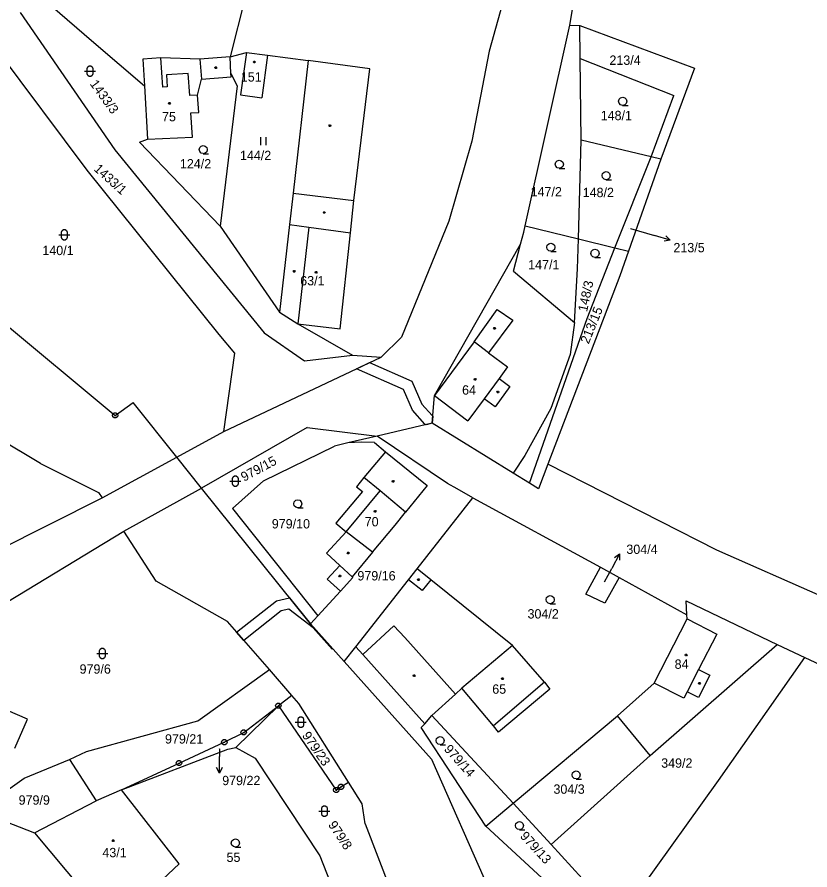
# Model space of a CAD drawing. Extents: x -850689 to -847910, y -1058374 to -1054747.
# Drawn here: x -849126.6 to -848982.2, y -1056250.1 to -1056094.9 of the extents above; entities that cross this region are included whole.
import ezdxf

# ---------------------------------------------------------------- set-up
doc = ezdxf.new("R2010")
doc.units = 0
for name, color, linetype in [('KN_BREMENA', 7, 'Continuous'), ('KN_HRANICE', 7, 'Continuous'), ('KN_KULTURY', 7, 'Continuous'), ('KN_MEZNIKY', 7, 'Continuous'), ('KN_PARCELY', 7, 'Continuous'), ('KN_SLUCKY', 7, 'Continuous'), ('KN_STAVEBNI', 7, 'Continuous')]:
    doc.layers.add(name, color=color, linetype=linetype)

# ---------------------------------------------------------------- blocks, each defined once
blk = doc.blocks.new('304')
blk.add_lwpolyline([(0, 0), (-0.38, 0.1), (-0.65, 0.37), (-0.75, 0.74), (-0.65, 1.11), (-0.38, 1.38), (-0.01, 1.48), (0.36, 1.38), (0.63, 1.11), (0.73, 0.73), (0.63, 0.35), (0.36, 0.08), (-0.02, -0.02), (0.98, -0.02)])
blk = doc.blocks.new('306')
for p, q in [((-0.5, 1.5), (-0.5, 0)), ((0.5, 0), (0.5, 1.5))]:
    blk.add_line(p, q)
blk = doc.blocks.new('316')
for points in [[(-0.5, 1.5), (-0.4, 1.79), (-0.15, 1.97), (0.16, 1.97), (0.41, 1.79), (0.51, 1.5), (0.51, 0.5), (0.41, 0.21), (0.16, 0.03), (-0.15, 0.03), (-0.4, 0.21), (-0.5, 0.5), (-0.5, 1.5)], [(-1, 1), (0.27, 1), (1, 1)]]:
    blk.add_lwpolyline(points)
blk = doc.blocks.new('NAHRADNI_SYMBOL')
blk.add_lwpolyline([(0.09, 0.15), (0.18, 0), (0.09, -0.15), (-0.09, -0.15), (-0.18, 0), (-0.09, 0.15), (0.09, 0.15)])
blk = doc.blocks.new('10292')
blk.add_line((0, 3), (0, 0))
blk.add_lwpolyline([(-0.5, 2), (0, 3), (0.5, 2)])
blk = doc.blocks.new('402')
blk.add_lwpolyline([(0.09, 0.15), (0.18, 0), (0.09, -0.15), (-0.09, -0.15), (-0.18, 0), (-0.09, 0.15), (0.09, 0.15)])
blk = doc.blocks.new('105')
blk.add_line((-0.12, 0), (0.12, 0))
blk.add_lwpolyline([(0.15, 0.48), (0.4, 0.3), (0.5, 0.01), (0.4, -0.28), (0.15, -0.46), (-0.16, -0.46), (-0.41, -0.28), (-0.51, 0.01), (-0.41, 0.3), (-0.16, 0.48), (0.15, 0.48)])

msp = doc.modelspace()

# ---------------------------------------------------------------- linework, layer by layer
at = {"layer": 'KN_BREMENA'}
for points in [[(-849062.4, -1056157.81), (-849054.72, -1056161.15), (-849052.89, -1056165.38), (-849051.02, -1056167.45), (-849050.9, -1056167.53), (-849051.02, -1056168.85), (-849052.13, -1056169.11), (-849052.32, -1056168.99), (-849054.59, -1056166.48), (-849056.24, -1056162.67), (-849064.8, -1056158.95)], [(-849086.62, -1056206.83), (-849079.37, -1056201.13), (-849076.98, -1056200.6), (-849073.16, -1056205.36), (-849069.12, -1056209.87), (-849069.22, -1056209.96), (-849072.69, -1056206.09), (-849077.08, -1056202.67), (-849078.49, -1056202.99), (-849085.3, -1056208.34)]]:
    msp.add_lwpolyline(points, close=True, dxfattribs=at)
at = {"layer": 'KN_HRANICE'}
for p, q in [((-849061.59, -1055999.43), (-849087.8, -1056102.18)), ((-849026.02, -1056048.69), (-849040.65, -1056101.15)), ((-849025.96, -1056096.38), (-849019.75, -1056059.38)), ((-849125.98, -1056094.1), (-849108.8, -1056119.1)), ((-849120.52, -1056092.73), (-849112.59, -1056099.57)), ((-849113.79, -1056122.8), (-849134.65, -1056094.95)), ((-849034.09, -1056132.93), (-849025.96, -1056096.38)), ((-849025.96, -1056096.38), (-849024.15, -1056096.47)), ((-849024.15, -1056096.47), (-849003.24, -1056104.25)), ((-849024.08, -1056102.46), (-849024.15, -1056096.47)), ((-849112.59, -1056099.57), (-849103.4, -1056107.43)), ((-849087.8, -1056102.18), (-849084.8, -1056101.39)), ((-849084.8, -1056101.39), (-849085.87, -1056109.07)), ((-849084.8, -1056101.39), (-849081, -1056101.88)), ((-849081, -1056101.88), (-849082.02, -1056109.6)), ((-849081, -1056101.88), (-849073.57, -1056102.83)), ((-849040.65, -1056101.15), (-849043.77, -1056117.52)), ((-849100.4, -1056102.37), (-849103.68, -1056102.59)), ((-849103.68, -1056102.59), (-849103.4, -1056107.43)), ((-849093.28, -1056102.6), (-849100.4, -1056102.37)), ((-849087.8, -1056102.18), (-849093.28, -1056102.6)), ((-849087.64, -1056105.2), (-849087.8, -1056102.18)), ((-849073.57, -1056102.83), (-849076.34, -1056126.97)), ((-849062.38, -1056104.35), (-849073.57, -1056102.83)), ((-849024.08, -1056102.46), (-849007, -1056109.17)), ((-849023.9, -1056117.35), (-849024.08, -1056102.46)), ((-849065.26, -1056128.29), (-849062.38, -1056104.35)), ((-849003.24, -1056104.25), (-849009.36, -1056120.8)), ((-849093.72, -1056109.11), (-849092.99, -1056106.2)), ((-849092.99, -1056106.2), (-849087.61, -1056105.82)), ((-849087.61, -1056105.82), (-849087.64, -1056105.2)), ((-849087.64, -1056105.2), (-849086.51, -1056107.42)), ((-849103.4, -1056107.43), (-849102.84, -1056117.15)), ((-849086.51, -1056107.42), (-849089.63, -1056132.97)), ((-849093.51, -1056112.28), (-849093.72, -1056109.11)), ((-849085.87, -1056109.07), (-849082.02, -1056109.6)), ((-849011.17, -1056120.37), (-849007, -1056109.17)), ((-849094.92, -1056112.37), (-849093.51, -1056112.28)), ((-849094.63, -1056116.77), (-849094.92, -1056112.37)), ((-849104.3, -1056117.68), (-849102.84, -1056117.15)), ((-849102.84, -1056117.15), (-849094.63, -1056116.77)), ((-849024.4, -1056135.3), (-849023.9, -1056117.35)), ((-849011.17, -1056120.37), (-849023.9, -1056117.35)), ((-849104.3, -1056117.68), (-849089.63, -1056132.97)), ((-849043.77, -1056117.52), (-849047.99, -1056132.07)), ((-849108.8, -1056119.1), (-849081.6, -1056152.37)), ((-849017.73, -1056136.93), (-849011.17, -1056120.37)), ((-849009.36, -1056120.8), (-849011.17, -1056120.37)), ((-849009.36, -1056120.8), (-849015.25, -1056137.54)), ((-849089.76, -1056152.69), (-849113.79, -1056122.8)), ((-849076.34, -1056126.97), (-849076.99, -1056132.65)), ((-849065.89, -1056134.2), (-849065.26, -1056128.29)), ((-849089.63, -1056132.97), (-849078.82, -1056148.64)), ((-849076.99, -1056132.65), (-849078.82, -1056148.64)), ((-849047.99, -1056132.07), (-849056.6, -1056153.2)), ((-849034.34, -1056134.08), (-849034.09, -1056132.93)), ((-849034.09, -1056132.93), (-849024.4, -1056135.3)), ((-849067.76, -1056151.67), (-849065.89, -1056134.2)), ((-849034.91, -1056136.25), (-849034.34, -1056134.08)), ((-849024.55, -1056140.74), (-849024.4, -1056135.3)), ((-849024.4, -1056135.3), (-849017.73, -1056136.93)), ((-849050.56, -1056163.8), (-849034.91, -1056136.25)), ((-849036.2, -1056141.14), (-849034.91, -1056136.25)), ((-849022.82, -1056149.76), (-849017.73, -1056136.93)), ((-849017.73, -1056136.93), (-849015.25, -1056137.54)), ((-849015.25, -1056137.54), (-849016.83, -1056142.02)), ((-849025.13, -1056150.52), (-849024.55, -1056140.74)), ((-849036.2, -1056141.14), (-849025.13, -1056150.52)), ((-849016.83, -1056142.02), (-849029.93, -1056176.3)), ((-849136.05, -1056144.68), (-849108.72, -1056167.41)), ((-849078.82, -1056148.64), (-849075.49, -1056150.72)), ((-849033.29, -1056179.77), (-849022.82, -1056149.76)), ((-849075.49, -1056150.72), (-849065.52, -1056156.43)), ((-849075.49, -1056150.72), (-849067.76, -1056151.67)), ((-849025.13, -1056150.52), (-849025.89, -1056156.3)), ((-849086.95, -1056156.09), (-849089.76, -1056152.69)), ((-849081.6, -1056152.37), (-849074.26, -1056157.48)), ((-849060.28, -1056156.81), (-849056.6, -1056153.2)), ((-849088.95, -1056170.34), (-849086.95, -1056156.09)), ((-849088.95, -1056170.34), (-849060.28, -1056156.81)), ((-849074.26, -1056157.48), (-849065.52, -1056156.43)), ((-849065.52, -1056156.43), (-849060.28, -1056156.81)), ((-849025.89, -1056156.3), (-849029.4, -1056166.16)), ((-849051.02, -1056168.85), (-849050.56, -1056163.8)), ((-849108.72, -1056167.41), (-849105.46, -1056165.09)), ((-849097.52, -1056174.99), (-849105.46, -1056165.09)), ((-849029.4, -1056166.16), (-849034.13, -1056174.69)), ((-849073.74, -1056169.61), (-849092.97, -1056180.66)), ((-849073.74, -1056169.61), (-849061.03, -1056171.18)), ((-849051.02, -1056168.85), (-849061.03, -1056171.18)), ((-849036.26, -1056177.94), (-849051.02, -1056168.85)), ((-849122.32, -1056176.18), (-849130.07, -1056171.57)), ((-849097.52, -1056174.99), (-849088.95, -1056170.34)), ((-849061.03, -1056171.18), (-849066.39, -1056172.42)), ((-849048.23, -1056179.78), (-849061.03, -1056171.18)), ((-849081.7, -1056179.33), (-849068.77, -1056173.01)), ((-849066.39, -1056172.42), (-849068.77, -1056173.01)), ((-849063.9, -1056172.26), (-849066.39, -1056172.42)), ((-849061.52, -1056172.32), (-849063.9, -1056172.26)), ((-849061.52, -1056172.32), (-849059.53, -1056174.06)), ((-849059.53, -1056174.06), (-849063.42, -1056178.73)), ((-849059.53, -1056174.06), (-849051.93, -1056180.18)), ((-849034.13, -1056174.69), (-849036.26, -1056177.94)), ((-849122.32, -1056176.18), (-849111.73, -1056181.42)), ((-849111.09, -1056182.39), (-849097.52, -1056174.99)), ((-849092.97, -1056180.66), (-849097.52, -1056174.99)), ((-849029.93, -1056176.3), (-849031.64, -1056180.79)), ((-848999.18, -1056191.91), (-849029.93, -1056176.3)), ((-849033.29, -1056179.77), (-849036.26, -1056177.94)), ((-849081.7, -1056179.33), (-849087.37, -1056184.36)), ((-849063.42, -1056178.73), (-849064.78, -1056180.4)), ((-849107.15, -1056188.47), (-849092.97, -1056180.66)), ((-849073.16, -1056205.36), (-849092.97, -1056180.66)), ((-849064.78, -1056180.4), (-849063.7, -1056181.26)), ((-849051.93, -1056180.18), (-849055.88, -1056185.01)), ((-849046.44, -1056180.79), (-849048.23, -1056179.78)), ((-849043.62, -1056182.43), (-849046.44, -1056180.79)), ((-849031.64, -1056180.79), (-849033.29, -1056179.77)), ((-849139, -1056196.47), (-849111.09, -1056182.39)), ((-849111.73, -1056181.42), (-849111.09, -1056182.39)), ((-849063.7, -1056181.26), (-849068.52, -1056187.03)), ((-849053.77, -1056195.35), (-849043.62, -1056182.43)), ((-849043.62, -1056182.43), (-849020.34, -1056195)), ((-849087.37, -1056184.36), (-849071.8, -1056203.9)), ((-849057.72, -1056187.39), (-849055.88, -1056185.01)), ((-849068.52, -1056187.03), (-849066.67, -1056188.57)), ((-849139.2, -1056207.88), (-849107.15, -1056188.47)), ((-849101.23, -1056197.58), (-849107.15, -1056188.47)), ((-849066.67, -1056188.57), (-849070.27, -1056192.49)), ((-849061.86, -1056192.28), (-849057.72, -1056187.39)), ((-848980.22, -1056200.29), (-848999.18, -1056191.91)), ((-849070.27, -1056192.49), (-849067.84, -1056194.72)), ((-849061.86, -1056192.28), (-849065.56, -1056196.81)), ((-849067.84, -1056194.72), (-849070.1, -1056197.19)), ((-849023.06, -1056199.93), (-849020.34, -1056195)), ((-849020.34, -1056195), (-849016.98, -1056196.89)), ((-849055.32, -1056197.33), (-849053.77, -1056195.35)), ((-849051.27, -1056197.35), (-849053.77, -1056195.35)), ((-849088.27, -1056204.94), (-849101.23, -1056197.58)), ((-849070.1, -1056197.19), (-849067.67, -1056199.42)), ((-849067.67, -1056199.42), (-849065.44, -1056196.92)), ((-849065.44, -1056196.92), (-849065.56, -1056196.81)), ((-849064.9, -1056209.52), (-849055.32, -1056197.33)), ((-849036.38, -1056209.25), (-849051.27, -1056197.35)), ((-849016.98, -1056196.89), (-849019.59, -1056201.6)), ((-849016.98, -1056196.89), (-849004.65, -1056203.72)), ((-849071.8, -1056203.9), (-849067.67, -1056199.42)), ((-849019.59, -1056201.6), (-849023.06, -1056199.93)), ((-849004.65, -1056203.72), (-849004.8, -1056201.15)), ((-849004.8, -1056201.15), (-848988.18, -1056209.07)), ((-849073.16, -1056205.36), (-849071.8, -1056203.9)), ((-849004.61, -1056204.42), (-849004.65, -1056203.72)), ((-849080.65, -1056213.66), (-849088.27, -1056204.94)), ((-849067.02, -1056212.21), (-849073.16, -1056205.36)), ((-849010.57, -1056216.16), (-849004.61, -1056204.42)), ((-849067.02, -1056212.21), (-849064.9, -1056209.52)), ((-849063.66, -1056210.9), (-849064.9, -1056209.52)), ((-849030.55, -1056215.98), (-849036.38, -1056209.25)), ((-849011.33, -1056229.27), (-848988.18, -1056209.07)), ((-848988.18, -1056209.07), (-848983.18, -1056211.44)), ((-849063.66, -1056210.9), (-849052.37, -1056223.51)), ((-848998.88, -1056233.84), (-848983.18, -1056211.44)), ((-848983.18, -1056211.44), (-848968.74, -1056218.34)), ((-849093.67, -1056222.96), (-849080.65, -1056213.66)), ((-849076.56, -1056218.35), (-849080.65, -1056213.66)), ((-849051.11, -1056229.98), (-849067.02, -1056212.21)), ((-849030.55, -1056215.98), (-849029.6, -1056217.21)), ((-849017.27, -1056222.1), (-849010.57, -1056216.16)), ((-849076.56, -1056218.35), (-849078.99, -1056220.24)), ((-849075.26, -1056219.83), (-849076.56, -1056218.35)), ((-849051.05, -1056222.04), (-849046.74, -1056218.12)), ((-849046.74, -1056218.12), (-849045.63, -1056217.05)), ((-849039.83, -1056223.87), (-849045.63, -1056217.05)), ((-849029.6, -1056217.21), (-849038.92, -1056225.07)), ((-849124.65, -1056222.67), (-849132.6, -1056219.32)), ((-849066.25, -1056234.12), (-849075.26, -1056219.83)), ((-849086.74, -1056227.86), (-849078.99, -1056220.24)), ((-849085.32, -1056225.1), (-849078.99, -1056220.24)), ((-849078.99, -1056220.24), (-849068.47, -1056235.58)), ((-849126.97, -1056227.99), (-849124.65, -1056222.67)), ((-849113.95, -1056228.54), (-849093.67, -1056222.96)), ((-849052.37, -1056223.51), (-849051.05, -1056222.04)), ((-849051.05, -1056222.04), (-849036.29, -1056237.99)), ((-849036.29, -1056237.99), (-849017.27, -1056222.1)), ((-849011.33, -1056229.27), (-849017.27, -1056222.1)), ((-849053.01, -1056224.22), (-849052.37, -1056223.51)), ((-849041.27, -1056242.15), (-849053.01, -1056224.22)), ((-849038.92, -1056225.07), (-849039.83, -1056223.87)), ((-849088.85, -1056226.88), (-849085.32, -1056225.1)), ((-849097.09, -1056230.68), (-849088.85, -1056226.88)), ((-849117.03, -1056230), (-849113.95, -1056228.54)), ((-849107.55, -1056235.54), (-849088.19, -1056228.17)), ((-849088.19, -1056228.17), (-849086.74, -1056227.86)), ((-849086.74, -1056227.86), (-849083.2, -1056229.78)), ((-849125.31, -1056233.41), (-849117.03, -1056230)), ((-849117.03, -1056230), (-849112.15, -1056237.55)), ((-849107.55, -1056235.54), (-849097.09, -1056230.68)), ((-849083.2, -1056229.78), (-849071.44, -1056247.58)), ((-849051.11, -1056229.98), (-849034.65, -1056267.35)), ((-849029.32, -1056245.51), (-849011.33, -1056229.27)), ((-849133.63, -1056239.4), (-849125.31, -1056233.41)), ((-849016.97, -1056259.04), (-848998.88, -1056233.84)), ((-849068.47, -1056235.58), (-849067.62, -1056235.02)), ((-849067.62, -1056235.02), (-849066.25, -1056234.12)), ((-849063.75, -1056238.1), (-849066.25, -1056234.12)), ((-849107.55, -1056235.54), (-849112.15, -1056237.55)), ((-849097.09, -1056249.01), (-849107.55, -1056235.54)), ((-849123.4, -1056243.38), (-849112.15, -1056237.55)), ((-849063.18, -1056241.7), (-849063.75, -1056238.1)), ((-849041.27, -1056242.15), (-849036.29, -1056237.99)), ((-849036.29, -1056237.99), (-849029.32, -1056245.51)), ((-849133.63, -1056239.4), (-849123.4, -1056243.38)), ((-849063.18, -1056241.7), (-849055.56, -1056261.61)), ((-849026.95, -1056255.29), (-849041.27, -1056242.15)), ((-849123.4, -1056243.38), (-849109.14, -1056260.33)), ((-849029.32, -1056245.51), (-849016.97, -1056259.04)), ((-849071.44, -1056247.58), (-849066.2, -1056260.88)), ((-849109.14, -1056260.33), (-849097.09, -1056249.01))]:
    msp.add_line(p, q, dxfattribs=at)
at = {"layer": 'KN_PARCELY'}
for p, q in [((-849014.93, -1056133.38), (-849010.55, -1056134.67)), ((-849019.64, -1056197.68), (-849018.33, -1056195.26)), ((-849089.74, -1056228.07), (-849089.74, -1056229.48))]:
    msp.add_line(p, q, dxfattribs=at)
at = {"layer": 'KN_SLUCKY'}
for p, q in [((-849100.05, -1056107.66), (-849100.4, -1056102.37)), ((-849093.28, -1056102.6), (-849092.99, -1056106.2)), ((-849095.4, -1056105.2), (-849099.36, -1056105.46)), ((-849099.36, -1056105.46), (-849099.22, -1056107.61)), ((-849095.14, -1056109.2), (-849095.4, -1056105.2)), ((-849099.22, -1056107.61), (-849100.05, -1056107.66)), ((-849093.72, -1056109.11), (-849095.14, -1056109.2)), ((-849076.34, -1056126.97), (-849065.26, -1056128.29)), ((-849076.99, -1056132.65), (-849073.47, -1056133.14)), ((-849073.47, -1056133.14), (-849075.49, -1056150.72)), ((-849073.47, -1056133.14), (-849065.89, -1056134.2)), ((-849043.39, -1056154.05), (-849039.2, -1056148.16)), ((-849039.2, -1056148.16), (-849036.32, -1056150.09)), ((-849036.32, -1056150.09), (-849040.74, -1056156.02)), ((-849043.39, -1056154.05), (-849050.56, -1056163.8)), ((-849040.74, -1056156.02), (-849043.39, -1056154.05)), ((-849040.74, -1056156.02), (-849037.3, -1056158.59)), ((-849037.3, -1056158.59), (-849038.84, -1056160.69)), ((-849038.84, -1056160.69), (-849041.55, -1056164.39)), ((-849038.84, -1056160.69), (-849036.85, -1056162.15)), ((-849036.85, -1056162.15), (-849039.56, -1056165.85)), ((-849050.56, -1056163.8), (-849044.51, -1056168.42)), ((-849041.55, -1056164.39), (-849044.51, -1056168.42)), ((-849039.56, -1056165.85), (-849041.55, -1056164.39)), ((-849060.5, -1056181.16), (-849063.42, -1056178.73)), ((-849066.67, -1056188.57), (-849060.5, -1056181.16)), ((-849055.88, -1056185.01), (-849060.5, -1056181.16)), ((-849061.86, -1056192.28), (-849066.67, -1056188.57)), ((-849067.84, -1056194.72), (-849065.56, -1056196.81)), ((-849052.81, -1056199.3), (-849055.32, -1056197.33)), ((-849051.27, -1056197.35), (-849052.81, -1056199.3)), ((-849063.66, -1056210.9), (-849057.98, -1056205.7)), ((-849057.98, -1056205.7), (-849056.01, -1056207.85)), ((-849004.61, -1056204.42), (-848999.2, -1056207.22)), ((-848999.2, -1056207.22), (-849002.51, -1056213.62)), ((-849046.74, -1056218.12), (-849056.01, -1056207.85)), ((-849036.38, -1056209.25), (-849045.63, -1056217.05)), ((-849002.51, -1056213.62), (-849004.6, -1056217.72)), ((-849002.51, -1056213.62), (-849000.47, -1056214.7)), ((-849000.47, -1056214.7), (-849002.54, -1056218.77)), ((-849030.55, -1056215.98), (-849039.83, -1056223.87)), ((-849005.19, -1056218.89), (-849010.57, -1056216.16)), ((-849004.6, -1056217.72), (-849005.19, -1056218.89)), ((-849002.54, -1056218.77), (-849004.6, -1056217.72))]:
    msp.add_line(p, q, dxfattribs=at)
at = {"layer": 'KN_STAVEBNI'}
for p, q in [((-849084.8, -1056101.39), (-849085.87, -1056109.07)), ((-849084.8, -1056101.39), (-849081, -1056101.88)), ((-849081, -1056101.88), (-849082.02, -1056109.6)), ((-849100.4, -1056102.37), (-849103.68, -1056102.59)), ((-849103.68, -1056102.59), (-849103.4, -1056107.43)), ((-849100.05, -1056107.66), (-849100.4, -1056102.37)), ((-849095.4, -1056105.2), (-849099.36, -1056105.46)), ((-849099.36, -1056105.46), (-849099.22, -1056107.61)), ((-849095.14, -1056109.2), (-849095.4, -1056105.2)), ((-849103.4, -1056107.43), (-849102.84, -1056117.15)), ((-849099.22, -1056107.61), (-849100.05, -1056107.66)), ((-849093.72, -1056109.11), (-849095.14, -1056109.2)), ((-849093.51, -1056112.28), (-849093.72, -1056109.11)), ((-849085.87, -1056109.07), (-849082.02, -1056109.6)), ((-849094.92, -1056112.37), (-849093.51, -1056112.28)), ((-849094.63, -1056116.77), (-849094.92, -1056112.37)), ((-849102.84, -1056117.15), (-849094.63, -1056116.77)), ((-849073.47, -1056133.14), (-849075.49, -1056150.72)), ((-849073.47, -1056133.14), (-849065.89, -1056134.2)), ((-849067.76, -1056151.67), (-849065.89, -1056134.2)), ((-849075.49, -1056150.72), (-849067.76, -1056151.67)), ((-849043.39, -1056154.05), (-849050.56, -1056163.8)), ((-849040.74, -1056156.02), (-849043.39, -1056154.05)), ((-849040.74, -1056156.02), (-849037.3, -1056158.59)), ((-849037.3, -1056158.59), (-849038.84, -1056160.69)), ((-849038.84, -1056160.69), (-849041.55, -1056164.39)), ((-849050.56, -1056163.8), (-849044.51, -1056168.42)), ((-849041.55, -1056164.39), (-849044.51, -1056168.42)), ((-849066.67, -1056188.57), (-849060.5, -1056181.16)), ((-849055.88, -1056185.01), (-849060.5, -1056181.16)), ((-849057.72, -1056187.39), (-849055.88, -1056185.01)), ((-849061.86, -1056192.28), (-849066.67, -1056188.57)), ((-849061.86, -1056192.28), (-849057.72, -1056187.39)), ((-849010.57, -1056216.16), (-849004.61, -1056204.42)), ((-849004.61, -1056204.42), (-848999.2, -1056207.22)), ((-848999.2, -1056207.22), (-849002.51, -1056213.62)), ((-849036.38, -1056209.25), (-849045.63, -1056217.05)), ((-849030.55, -1056215.98), (-849036.38, -1056209.25)), ((-849002.51, -1056213.62), (-849004.6, -1056217.72)), ((-849030.55, -1056215.98), (-849039.83, -1056223.87)), ((-849005.19, -1056218.89), (-849010.57, -1056216.16)), ((-849039.83, -1056223.87), (-849045.63, -1056217.05)), ((-849004.6, -1056217.72), (-849005.19, -1056218.89))]:
    msp.add_line(p, q, dxfattribs=at)

# ---------------------------------------------------------------- block references
at = {"layer": 'KN_KULTURY'}
for name, p in [('402', (-849083.38, -1056103.13)), ('316', (-849113.3, -1056105.78)), ('402', (-849090.4, -1056104.11)), ('304', (-849016.32, -1056110.99)), ('402', (-849098.85, -1056110.61)), ('402', (-849069.62, -1056114.71)), ('306', (-849081.75, -1056118.26)), ('304', (-849092.68, -1056119.77)), ('304', (-849027.86, -1056122.44)), ('304', (-849019.33, -1056124.52)), ('402', (-849070.65, -1056130.49)), ('316', (-849117.96, -1056135.54)), ('304', (-849029.4, -1056137.55)), ('304', (-849021.36, -1056138.66)), ('402', (-849076.13, -1056141.21)), ('402', (-849072.14, -1056141.35)), ('402', (-849039.66, -1056151.59)), ('402', (-849043.21, -1056160.85)), ('402', (-849039.05, -1056163.18)), ('316', (-849086.86, -1056180.39)), ('402', (-849058.12, -1056179.41)), ('304', (-849075.47, -1056184.23)), ('402', (-849061.41, -1056184.89)), ('402', (-849066.29, -1056192.42)), ('402', (-849067.79, -1056196.61)), ('402', (-849053.51, -1056197.31)), ('304', (-849029.52, -1056201.67)), ('316', (-849111.06, -1056211.71)), ('402', (-849004.79, -1056211)), ('402', (-849054.29, -1056214.74)), ('402', (-849038.21, -1056215.3)), ('402', (-849002.36, -1056216.16)), ('316', (-849074.92, -1056224.23)), ('304', (-849049.55, -1056227.32)), ('304', (-849024.8, -1056233.56)), ('316', (-849070.62, -1056240.42)), ('304', (-849035.12, -1056242.78)), ('NAHRADNI_SYMBOL', (-849109.08, -1056244.77)), ('304', (-849086.82, -1056245.96))]:
    msp.add_blockref(name, p, dxfattribs=at)
at = {"layer": 'KN_MEZNIKY'}
for p in [(-849108.72, -1056167.41), (-849078.99, -1056220.24), (-849085.32, -1056225.1), (-849088.85, -1056226.88), (-849097.09, -1056230.68), (-849068.47, -1056235.58), (-849067.62, -1056235.02)]:
    msp.add_blockref('105', p, dxfattribs=at)
at = {"layer": 'KN_PARCELY'}
for p, rotation in [((-849010.55, -1056134.67), -106.466176), ((-849018.33, -1056195.26), -28.429324), ((-849089.74, -1056229.48), -179.97666100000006)]:
    msp.add_blockref('10292', p, dxfattribs=dict(at, rotation=rotation))

# ---------------------------------------------------------------- texts
for s, height, p in [('213/4', 1.7, (-849018.74, -1056103.62)), ('151', 1.7, (-849085.84, -1056106.67)), ('75', 1.7, (-849100.19, -1056113.9)), ('148/1', 1.7, (-849020.33, -1056113.69)), ('144/2', 1.7, (-849086, -1056120.96)), ('124/2', 1.7, (-849096.93, -1056122.47)), ('147/2', 1.7, (-849033.09, -1056127.56)), ('148/2', 1.7, (-849023.61, -1056127.69)), ('213/5', 0.1, (-849015.26, -1056133.56)), ('213/5', 1.7, (-849007.09, -1056137.73)), ('140/1', 1.7, (-849121.97, -1056138.24)), ('147/1', 1.7, (-849033.53, -1056140.83)), ('63/1', 1.7, (-849075.03, -1056143.75)), ('64', 1.7, (-849045.56, -1056163.63)), ('979/10', 1.7, (-849080.2, -1056187.98)), ('70', 1.7, (-849063.29, -1056187.6)), ('304/4', 1.7, (-849015.66, -1056192.62)), ('979/16', 1.7, (-849064.62, -1056197.44)), ('304/4', 0.1, (-849019.89, -1056197.68)), ('304/2', 1.7, (-849033.65, -1056204.37)), ('84', 1.7, (-849006.87, -1056213.52)), ('979/6', 1.7, (-849115.19, -1056214.41)), ('65', 1.7, (-849040.07, -1056218.06)), ('979/21', 1.7, (-849099.64, -1056227.13)), ('979/22', 0.1, (-849090.03, -1056228.07)), ('349/2', 1.7, (-849009.32, -1056231.52)), ('979/22', 1.7, (-849089.23, -1056234.69)), ('304/3', 1.7, (-849028.93, -1056236.26)), ('979/9', 1.7, (-849126.29, -1056238.25)), ('43/1', 1.7, (-849111.04, -1056247.81)), ('55', 1.7, (-849088.44, -1056248.66))]:
    msp.add_text(s, height=height, dxfattribs=at).set_placement(p)
for s, rotation, p in [('1433/3', 305.902, (-849113.4, -1056107.09)), ('1433/1', 317.992, (-849112.72, -1056122.73)), ('148/3', 78.037, (-849022.82, -1056148.66)), ('213/15', 67.838, (-849022.53, -1056154.52)), ('979/15', 28.361, (-849085.26, -1056179.5)), ('979/23', 304.756, (-849074.78, -1056225.67)), ('979/14', 311.976, (-849048.96, -1056228.23)), ('979/8', 303.496, (-849070.02, -1056241.89)), ('979/13', 312.434, (-849035.12, -1056244.05))]:
    msp.add_text(s, height=1.7, rotation=rotation, dxfattribs=at).set_placement(p)

doc.saveas('drawing.dxf')
